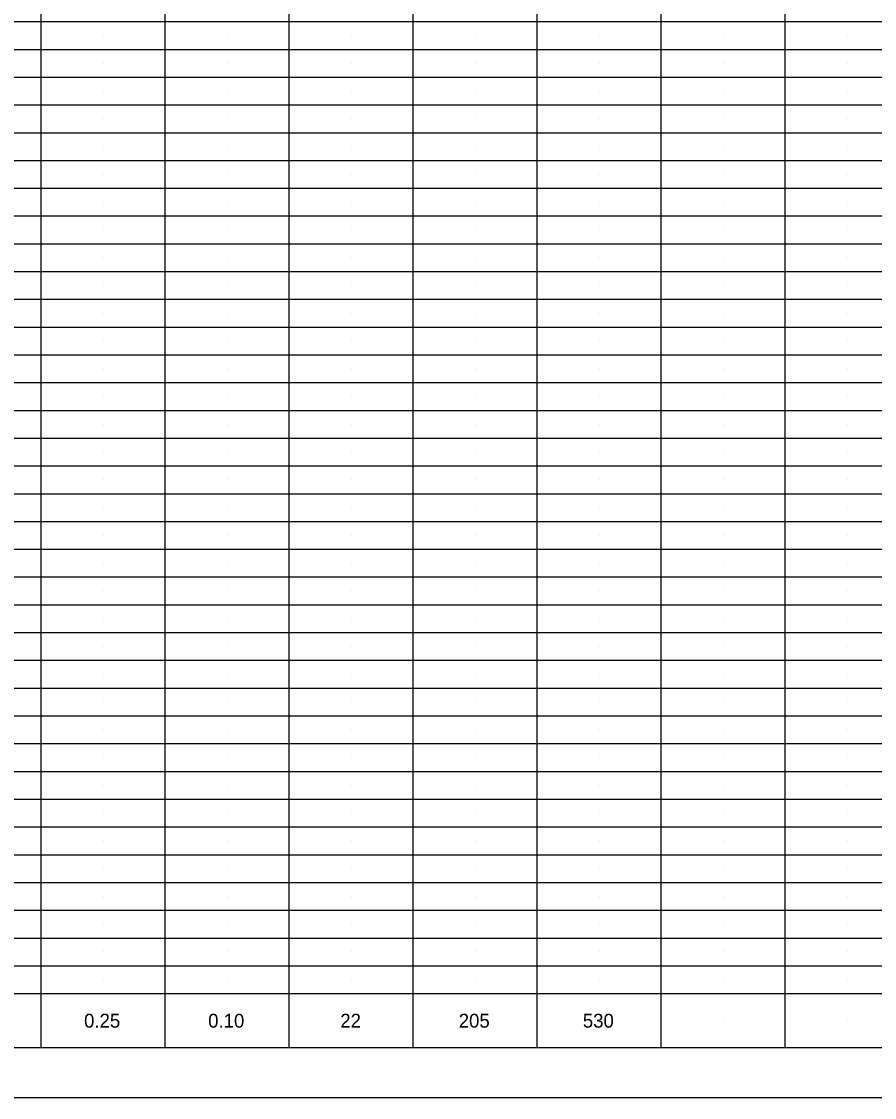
# Model space of a CAD drawing. Extents: x 0 to 66.4, y -22.2 to 22.
# Drawn here: x 16.8 to 25.4, y 0 to 10.85 of the extents above; entities that cross this region are included whole.
import ezdxf

# ---------------------------------------------------------------- set-up
doc = ezdxf.new("R2010")
doc.units = 0
for name, color, linetype in [('RD_P_Text', 7, 'Continuous'), ('SC_Scratch1', 7, 'Continuous'), ('SC_Scratch3', 7, 'Continuous'), ('SH_Border', 7, 'Continuous'), ('SH_Cut_Line', 7, 'Continuous'), ('SH_Data', 7, 'Continuous')]:
    doc.layers.add(name, color=color, linetype=linetype)

msp = doc.modelspace()

# ---------------------------------------------------------------- linework, layer by layer
at = {"layer": 'SC_Scratch1'}
for p, q in [((17.625, 10.708), (17.625, 10.708)), ((18.875, 10.708), (18.875, 10.708)), ((20.125, 10.708), (20.125, 10.708)), ((21.375, 10.708), (21.375, 10.708)), ((22.625, 10.708), (22.625, 10.708)), ((23.875, 10.708), (23.875, 10.708)), ((25.125, 10.708), (25.125, 10.708)), ((17.625, 10.428), (17.625, 10.428)), ((18.875, 10.428), (18.875, 10.428)), ((20.125, 10.428), (20.125, 10.428)), ((21.375, 10.428), (21.375, 10.428)), ((22.625, 10.428), (22.625, 10.428)), ((23.875, 10.428), (23.875, 10.428)), ((25.125, 10.428), (25.125, 10.428)), ((17.625, 10.148), (17.625, 10.148)), ((18.875, 10.148), (18.875, 10.148)), ((20.125, 10.148), (20.125, 10.148)), ((21.375, 10.148), (21.375, 10.148)), ((22.625, 10.148), (22.625, 10.148)), ((23.875, 10.148), (23.875, 10.148)), ((25.125, 10.148), (25.125, 10.148)), ((17.625, 9.868), (17.625, 9.868)), ((18.875, 9.868), (18.875, 9.868)), ((20.125, 9.868), (20.125, 9.868)), ((21.375, 9.868), (21.375, 9.868)), ((22.625, 9.868), (22.625, 9.868)), ((23.875, 9.868), (23.875, 9.868)), ((25.125, 9.868), (25.125, 9.868)), ((17.625, 9.588), (17.625, 9.588)), ((18.875, 9.588), (18.875, 9.588)), ((20.125, 9.588), (20.125, 9.588)), ((21.375, 9.588), (21.375, 9.588)), ((22.625, 9.588), (22.625, 9.588)), ((23.875, 9.588), (23.875, 9.588)), ((25.125, 9.588), (25.125, 9.588)), ((17.625, 9.308), (17.625, 9.308)), ((18.875, 9.308), (18.875, 9.308)), ((20.125, 9.308), (20.125, 9.308)), ((21.375, 9.308), (21.375, 9.308)), ((22.625, 9.308), (22.625, 9.308)), ((23.875, 9.308), (23.875, 9.308)), ((25.125, 9.308), (25.125, 9.308)), ((17.625, 9.028), (17.625, 9.028)), ((18.875, 9.028), (18.875, 9.028)), ((20.125, 9.028), (20.125, 9.028)), ((21.375, 9.028), (21.375, 9.028)), ((22.625, 9.028), (22.625, 9.028)), ((23.875, 9.028), (23.875, 9.028)), ((25.125, 9.028), (25.125, 9.028)), ((17.625, 8.748), (17.625, 8.748)), ((18.875, 8.748), (18.875, 8.748)), ((20.125, 8.748), (20.125, 8.748)), ((21.375, 8.748), (21.375, 8.748)), ((22.625, 8.748), (22.625, 8.748)), ((23.875, 8.748), (23.875, 8.748)), ((25.125, 8.748), (25.125, 8.748)), ((17.625, 8.468), (17.625, 8.468)), ((18.875, 8.468), (18.875, 8.468)), ((20.125, 8.468), (20.125, 8.468)), ((21.375, 8.468), (21.375, 8.468)), ((22.625, 8.468), (22.625, 8.468)), ((23.875, 8.468), (23.875, 8.468)), ((25.125, 8.468), (25.125, 8.468)), ((17.625, 8.188), (17.625, 8.188)), ((18.875, 8.188), (18.875, 8.188)), ((20.125, 8.188), (20.125, 8.188)), ((21.375, 8.188), (21.375, 8.188)), ((22.625, 8.188), (22.625, 8.188)), ((23.875, 8.188), (23.875, 8.188)), ((25.125, 8.188), (25.125, 8.188)), ((17.625, 7.908), (17.625, 7.908)), ((18.875, 7.908), (18.875, 7.908)), ((20.125, 7.908), (20.125, 7.908)), ((21.375, 7.908), (21.375, 7.908)), ((22.625, 7.908), (22.625, 7.908)), ((23.875, 7.908), (23.875, 7.908)), ((25.125, 7.908), (25.125, 7.908)), ((17.625, 7.628), (17.625, 7.628)), ((18.875, 7.628), (18.875, 7.628)), ((20.125, 7.628), (20.125, 7.628)), ((21.375, 7.628), (21.375, 7.628)), ((22.625, 7.628), (22.625, 7.628)), ((23.875, 7.628), (23.875, 7.628)), ((25.125, 7.628), (25.125, 7.628)), ((17.625, 7.348), (17.625, 7.348)), ((18.875, 7.348), (18.875, 7.348)), ((20.125, 7.348), (20.125, 7.348)), ((21.375, 7.348), (21.375, 7.348)), ((22.625, 7.348), (22.625, 7.348)), ((23.875, 7.348), (23.875, 7.348)), ((25.125, 7.348), (25.125, 7.348)), ((17.625, 7.068), (17.625, 7.068)), ((18.875, 7.068), (18.875, 7.068)), ((20.125, 7.068), (20.125, 7.068)), ((21.375, 7.068), (21.375, 7.068)), ((22.625, 7.068), (22.625, 7.068)), ((23.875, 7.068), (23.875, 7.068)), ((25.125, 7.068), (25.125, 7.068)), ((17.625, 6.788), (17.625, 6.788)), ((18.875, 6.788), (18.875, 6.788)), ((20.125, 6.788), (20.125, 6.788)), ((21.375, 6.788), (21.375, 6.788)), ((22.625, 6.788), (22.625, 6.788)), ((23.875, 6.788), (23.875, 6.788)), ((25.125, 6.788), (25.125, 6.788)), ((17.625, 6.508), (17.625, 6.508)), ((18.875, 6.508), (18.875, 6.508)), ((20.125, 6.508), (20.125, 6.508)), ((21.375, 6.508), (21.375, 6.508)), ((22.625, 6.508), (22.625, 6.508)), ((23.875, 6.508), (23.875, 6.508)), ((25.125, 6.508), (25.125, 6.508)), ((17.625, 6.228), (17.625, 6.228)), ((18.875, 6.228), (18.875, 6.228)), ((20.125, 6.228), (20.125, 6.228)), ((21.375, 6.228), (21.375, 6.228)), ((22.625, 6.228), (22.625, 6.228)), ((23.875, 6.228), (23.875, 6.228)), ((25.125, 6.228), (25.125, 6.228)), ((17.625, 5.948), (17.625, 5.948)), ((18.875, 5.948), (18.875, 5.948)), ((20.125, 5.948), (20.125, 5.948)), ((21.375, 5.948), (21.375, 5.948)), ((22.625, 5.948), (22.625, 5.948)), ((23.875, 5.948), (23.875, 5.948)), ((25.125, 5.948), (25.125, 5.948)), ((17.625, 5.668), (17.625, 5.668)), ((18.875, 5.668), (18.875, 5.668)), ((20.125, 5.668), (20.125, 5.668)), ((21.375, 5.668), (21.375, 5.668)), ((22.625, 5.668), (22.625, 5.668)), ((23.875, 5.668), (23.875, 5.668)), ((25.125, 5.668), (25.125, 5.668)), ((17.625, 5.388), (17.625, 5.388)), ((18.875, 5.388), (18.875, 5.388)), ((20.125, 5.388), (20.125, 5.388)), ((21.375, 5.388), (21.375, 5.388)), ((22.625, 5.388), (22.625, 5.388)), ((23.875, 5.388), (23.875, 5.388)), ((25.125, 5.388), (25.125, 5.388)), ((17.625, 5.108), (17.625, 5.108)), ((18.875, 5.108), (18.875, 5.108)), ((20.125, 5.108), (20.125, 5.108)), ((21.375, 5.108), (21.375, 5.108)), ((22.625, 5.108), (22.625, 5.108)), ((23.875, 5.108), (23.875, 5.108)), ((25.125, 5.108), (25.125, 5.108)), ((17.625, 4.828), (17.625, 4.828)), ((18.875, 4.828), (18.875, 4.828)), ((20.125, 4.828), (20.125, 4.828)), ((21.375, 4.828), (21.375, 4.828)), ((22.625, 4.828), (22.625, 4.828)), ((23.875, 4.828), (23.875, 4.828)), ((25.125, 4.828), (25.125, 4.828)), ((17.625, 4.548), (17.625, 4.548)), ((18.875, 4.548), (18.875, 4.548)), ((20.125, 4.548), (20.125, 4.548)), ((21.375, 4.548), (21.375, 4.548)), ((22.625, 4.548), (22.625, 4.548)), ((23.875, 4.548), (23.875, 4.548)), ((25.125, 4.548), (25.125, 4.548)), ((17.625, 4.268), (17.625, 4.268)), ((18.875, 4.268), (18.875, 4.268)), ((20.125, 4.268), (20.125, 4.268)), ((21.375, 4.268), (21.375, 4.268)), ((22.625, 4.268), (22.625, 4.268)), ((23.875, 4.268), (23.875, 4.268)), ((25.125, 4.268), (25.125, 4.268)), ((17.625, 3.988), (17.625, 3.988)), ((18.875, 3.988), (18.875, 3.988)), ((20.125, 3.988), (20.125, 3.988)), ((21.375, 3.988), (21.375, 3.988)), ((22.625, 3.988), (22.625, 3.988)), ((23.875, 3.988), (23.875, 3.988)), ((25.125, 3.988), (25.125, 3.988)), ((17.625, 3.708), (17.625, 3.708)), ((18.875, 3.708), (18.875, 3.708)), ((20.125, 3.708), (20.125, 3.708)), ((21.375, 3.708), (21.375, 3.708)), ((22.625, 3.708), (22.625, 3.708)), ((23.875, 3.708), (23.875, 3.708)), ((25.125, 3.708), (25.125, 3.708)), ((17.625, 3.428), (17.625, 3.428)), ((18.875, 3.428), (18.875, 3.428)), ((20.125, 3.428), (20.125, 3.428)), ((21.375, 3.428), (21.375, 3.428)), ((22.625, 3.428), (22.625, 3.428)), ((23.875, 3.428), (23.875, 3.428)), ((25.125, 3.428), (25.125, 3.428)), ((17.625, 3.148), (17.625, 3.148)), ((18.875, 3.148), (18.875, 3.148)), ((20.125, 3.148), (20.125, 3.148)), ((21.375, 3.148), (21.375, 3.148)), ((22.625, 3.148), (22.625, 3.148)), ((23.875, 3.148), (23.875, 3.148)), ((25.125, 3.148), (25.125, 3.148)), ((17.625, 2.868), (17.625, 2.868)), ((18.875, 2.868), (18.875, 2.868)), ((20.125, 2.868), (20.125, 2.868)), ((21.375, 2.868), (21.375, 2.868)), ((22.625, 2.868), (22.625, 2.868)), ((23.875, 2.868), (23.875, 2.868)), ((25.125, 2.868), (25.125, 2.868)), ((17.625, 2.588), (17.625, 2.588)), ((18.875, 2.588), (18.875, 2.588)), ((20.125, 2.588), (20.125, 2.588)), ((21.375, 2.588), (21.375, 2.588)), ((22.625, 2.588), (22.625, 2.588)), ((23.875, 2.588), (23.875, 2.588)), ((25.125, 2.588), (25.125, 2.588)), ((17.625, 2.308), (17.625, 2.308)), ((18.875, 2.308), (18.875, 2.308)), ((20.125, 2.308), (20.125, 2.308)), ((21.375, 2.308), (21.375, 2.308)), ((22.625, 2.308), (22.625, 2.308)), ((23.875, 2.308), (23.875, 2.308)), ((25.125, 2.308), (25.125, 2.308)), ((17.625, 2.028), (17.625, 2.028)), ((18.875, 2.028), (18.875, 2.028)), ((20.125, 2.028), (20.125, 2.028)), ((21.375, 2.028), (21.375, 2.028)), ((22.625, 2.028), (22.625, 2.028)), ((23.875, 2.028), (23.875, 2.028)), ((25.125, 2.028), (25.125, 2.028)), ((17.625, 1.748), (17.625, 1.748)), ((18.875, 1.748), (18.875, 1.748)), ((20.125, 1.748), (20.125, 1.748)), ((21.375, 1.748), (21.375, 1.748)), ((22.625, 1.748), (22.625, 1.748)), ((23.875, 1.748), (23.875, 1.748)), ((25.125, 1.748), (25.125, 1.748)), ((17.625, 1.468), (17.625, 1.468)), ((18.875, 1.468), (18.875, 1.468)), ((20.125, 1.468), (20.125, 1.468)), ((21.375, 1.468), (21.375, 1.468)), ((22.625, 1.468), (22.625, 1.468)), ((23.875, 1.468), (23.875, 1.468)), ((25.125, 1.468), (25.125, 1.468)), ((17.625, 1.188), (17.625, 1.188)), ((18.875, 1.188), (18.875, 1.188)), ((20.125, 1.188), (20.125, 1.188)), ((21.375, 1.188), (21.375, 1.188)), ((22.625, 1.188), (22.625, 1.188)), ((23.875, 1.188), (23.875, 1.188)), ((25.125, 1.188), (25.125, 1.188))]:
    msp.add_line(p, q, dxfattribs=at)
at = {"layer": 'SC_Scratch3'}
for p, q in [((17.625, 0.774), (17.625, 0.774)), ((18.875, 0.774), (18.875, 0.774)), ((20.125, 0.774), (20.125, 0.774)), ((21.375, 0.774), (21.375, 0.774)), ((22.625, 0.774), (22.625, 0.774)), ((23.875, 0.774), (23.875, 0.774)), ((25.125, 0.774), (25.125, 0.774))]:
    msp.add_line(p, q, dxfattribs=at)
at = {"layer": 'SH_Border'}
msp.add_lwpolyline([(1.5, 21.5), (33.5, 21.5), (33.5, 0.5), (1.5, 0.5)], close=True, dxfattribs=at)
at = {"layer": 'SH_Cut_Line'}
msp.add_lwpolyline([(0, 0), (34, 0), (34, 22), (0, 22)], close=True, dxfattribs=at)
at = {"layer": 'SH_Data'}
for p, q in [((17, 0.5), (17, 21.5)), ((18.25, 0.5), (18.25, 21.5)), ((19.5, 0.5), (19.5, 21.5)), ((20.75, 0.5), (20.75, 21.5)), ((22, 0.5), (22, 21.5)), ((23.25, 0.5), (23.25, 21.5)), ((24.5, 0.5), (24.5, 21.5)), ((1.5, 10.848), (32, 10.848)), ((1.5, 10.568), (32, 10.568)), ((1.5, 10.288), (32, 10.288)), ((1.5, 10.008), (32, 10.008)), ((1.5, 9.728), (32, 9.728)), ((1.5, 9.448), (32, 9.448)), ((1.5, 9.168), (32, 9.168)), ((1.5, 8.888), (32, 8.888)), ((1.5, 8.608), (32, 8.608)), ((1.5, 8.328), (32, 8.328)), ((1.5, 8.048), (32, 8.048)), ((1.5, 7.768), (32, 7.768)), ((1.5, 7.488), (32, 7.488)), ((1.5, 7.208), (32, 7.208)), ((1.5, 6.928), (32, 6.928)), ((1.5, 6.648), (32, 6.648)), ((1.5, 6.368), (32, 6.368)), ((1.5, 6.088), (32, 6.088)), ((1.5, 5.808), (32, 5.808)), ((1.5, 5.528), (32, 5.528)), ((1.5, 5.248), (32, 5.248)), ((1.5, 4.968), (32, 4.968)), ((1.5, 4.688), (32, 4.688)), ((1.5, 4.408), (32, 4.408)), ((1.5, 4.128), (32, 4.128)), ((1.5, 3.848), (32, 3.848)), ((1.5, 3.568), (32, 3.568)), ((1.5, 3.288), (32, 3.288)), ((1.5, 3.008), (32, 3.008)), ((1.5, 2.728), (32, 2.728)), ((1.5, 2.448), (32, 2.448)), ((1.5, 2.168), (32, 2.168)), ((1.5, 1.888), (32, 1.888)), ((1.5, 1.608), (32, 1.608)), ((1.5, 1.328), (32, 1.328)), ((1.5, 1.048), (32, 1.048))]:
    msp.add_line(p, q, dxfattribs=at)

# ---------------------------------------------------------------- texts
at = {"layer": 'RD_P_Text'}
for s, p in [('0.25', (17.433, 0.704)), ('0.10', (18.684, 0.704)), ('22', (20.016, 0.704)), ('205', (21.21, 0.704)), ('530', (22.461, 0.704))]:
    msp.add_text(s, height=0.14, dxfattribs=at).set_placement(p)

doc.saveas('drawing.dxf')
